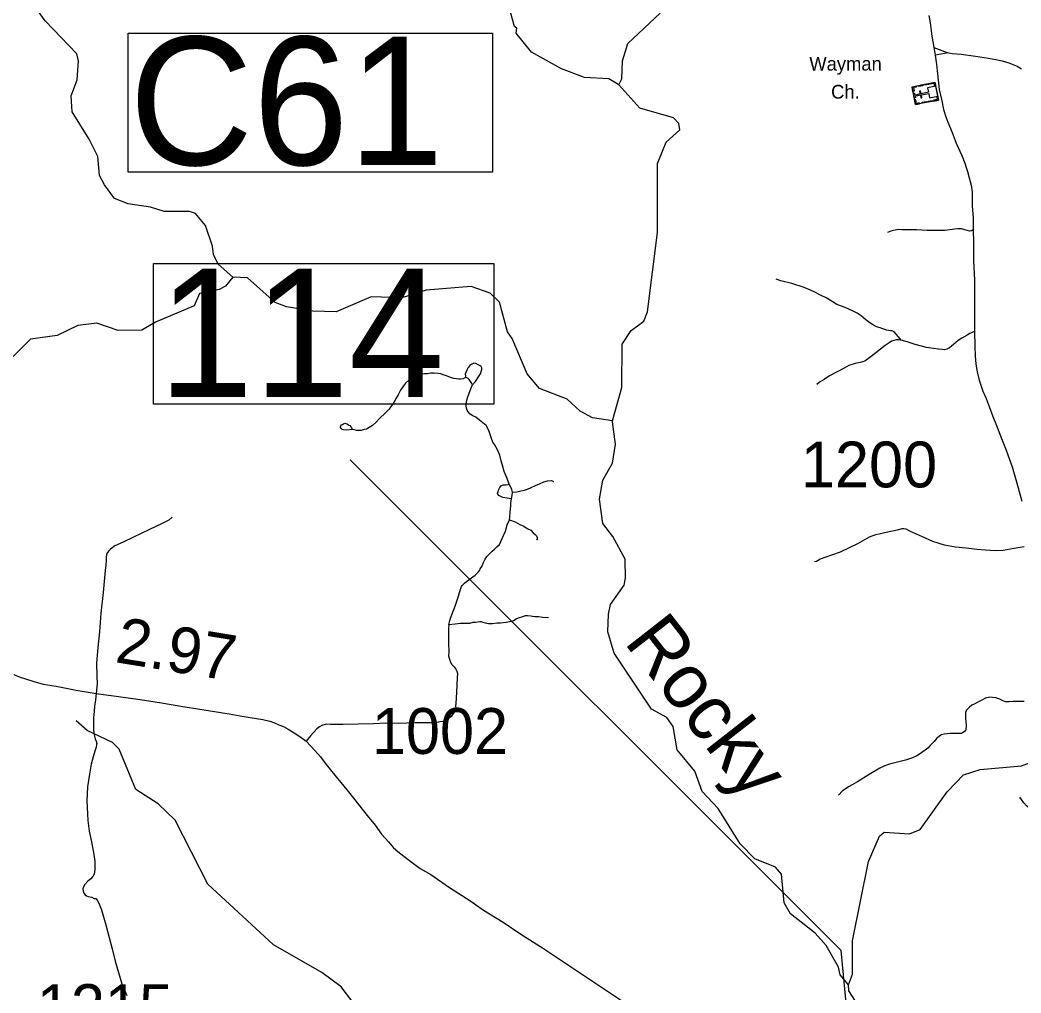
# Model space of a CAD drawing. Extents: x 2290615 to 2522933, y 819489 to 1012715.
# Drawn here: x 2342087 to 2353015, y 905808 to 916430 of the extents above; entities that cross this region are included whole.
import ezdxf

# ---------------------------------------------------------------- set-up
doc = ezdxf.new("R2010")
doc.units = 0
for name, color, linetype in [('Exist Cultural Church Label', 7, 'Continuous'), ('Exist Cultural Church with Cemetery CELL', 7, 'Continuous'), ('Exist Hydrographic Creek Single Shore', 7, 'Continuous'), ('Exist Hydrographic Creek Single Shore Label', 7, 'Continuous'), ('Exist Hydrographic Misc Water Feature', 7, 'Continuous'), ('Exist Road Non-System Type 51', 7, 'Continuous'), ('Exist Road Primary NC Structure Culvert Number Label', 7, 'Continuous'), ('Exist Road Secondary Mileage Hundredths English Label', 7, 'Continuous'), ('Exist Road Secondary Structure Standard Bridge Number Label', 7, 'Continuous'), ('Exist Road Secondary Type 51 Attributed', 7, 'Continuous'), ('Exist Road Secondary Type 51 Number Label', 7, 'Continuous')]:
    doc.layers.add(name, color=color, linetype=linetype)

msp = doc.modelspace()

# ---------------------------------------------------------------- linework, layer by layer
at = {"layer": 'Exist Cultural Church with Cemetery CELL'}
for points in [[(2351864, 915507), (2351827, 915702), (2352076, 915751), (2352114, 915555)], [(2351869, 915711), (2351871, 915699), (2351840, 915693), (2351847, 915654), (2351836, 915651), (2351827, 915702)], [(2352106, 915598), (2352085, 915708), (2351996, 915691), (2352006, 915641), (2351926, 915625), (2351919, 915658), (2351908, 915655), (2351915, 915623), (2351873, 915615), (2351876, 915604), (2351917, 915612), (2351923, 915579), (2351934, 915581), (2351928, 915614), (2352008, 915629), (2352017, 915580)], [(2351943, 915713), (2351900, 915705), (2351898, 915716), (2351941, 915725)], [(2352008, 915726), (2351965, 915718), (2351963, 915729), (2352006, 915737)], [(2352083, 915718), (2352072, 915716), (2352067, 915738), (2352028, 915730), (2352026, 915741), (2352076, 915751)], [(2351850, 915580), (2351840, 915630), (2351852, 915633), (2351862, 915582)], [(2351907, 915515), (2351905, 915526), (2351873, 915520), (2351866, 915560), (2351855, 915558), (2351864, 915507)], [(2351980, 915529), (2351937, 915521), (2351935, 915532), (2351978, 915540)], [(2352046, 915542), (2352003, 915534), (2352001, 915545), (2352044, 915553)], [(2352108, 915588), (2352097, 915586), (2352101, 915564), (2352061, 915556), (2352063, 915545), (2352114, 915555)]]:
    msp.add_lwpolyline(points, close=True, dxfattribs=at)
at = {"layer": 'Exist Hydrographic Creek Single Shore'}
for points in [[(2348626, 915722), (2348517, 915789), (2348250, 915801), (2347999, 915899), (2347672, 916080), (2347503, 916286), (2347511, 916342), (2347485, 916361), (2347398, 916676)], [(2348554, 912056), (2348657, 912418), (2348660, 912890), (2348758, 913042), (2348899, 913143), (2348939, 913243), (2349045, 914111), (2349045, 914863), (2349142, 915096), (2349290, 915230), (2349281, 915299), (2349222, 915362), (2348854, 915469), (2348626, 915722)], [(2351133, 905898), (2351040, 906006), (2351023, 906091), (2350887, 906328), (2350768, 906461), (2350499, 906673), (2350431, 906792), (2350402, 907106), (2350335, 907182), (2350109, 907271), (2349948, 907435), (2349710, 907823), (2349533, 908006), (2349456, 908229), (2349261, 908461), (2349216, 908718), (2349149, 908817), (2348981, 908906), (2348574, 909519), (2348504, 909749), (2348510, 909943), (2348534, 910049), (2348681, 910262), (2348697, 910335), (2348695, 910545), (2348558, 910792), (2348448, 910932), (2348412, 911200), (2348451, 911408), (2348557, 911593), (2348588, 911801), (2348556, 912045)], [(2351796, 904806), (2351134, 905833), (2351133, 905898)]]:
    msp.add_lwpolyline(points, dxfattribs=at)
at = {"layer": 'Exist Hydrographic Misc Water Feature'}
msp.add_line((2348556, 912045), (2348554, 912056), dxfattribs=at)
for points in [[(2344411, 913622), (2344251, 913763), (2344200, 913869), (2344190, 913961), (2344113, 914187), (2344003, 914317), (2343936, 914341), (2343661, 914340), (2343511, 914386), (2343268, 914425), (2343118, 914481), (2343008, 914631), (2342956, 914731), (2342937, 914940), (2342843, 915130), (2342656, 915427), (2342646, 915601), (2342711, 915778), (2342725, 915985), (2342707, 916060), (2342361, 916423), (2342192, 916662)], [(2348626, 915722), (2348659, 915789), (2348665, 915983), (2348721, 916175), (2349075, 916505)], [(2344411, 913622), (2344329, 913523), (2344263, 913488), (2344046, 913443), (2343990, 913309), (2343567, 913131), (2343418, 913046), (2343160, 913042), (2342926, 913121), (2342718, 913096), (2342494, 912985), (2342203, 912947), (2341775, 912526)], [(2348554, 912056), (2348336, 912086), (2348202, 912159), (2348059, 912291), (2347758, 912407), (2347623, 912569), (2347460, 912953), (2347409, 913026), (2347322, 913351), (2347221, 913448), (2347011, 913522), (2346520, 913482), (2346255, 913396), (2345921, 913408), (2345540, 913245), (2345282, 913251), (2344998, 913298), (2344873, 913346), (2344569, 913615), (2344411, 913622)], [(2345720, 905709), (2345594, 905875), (2345383, 906030), (2344855, 906333), (2344139, 906997), (2343781, 907694), (2343595, 907874), (2343352, 908031), (2343171, 908470), (2343095, 908543), (2342819, 908672), (2342701, 908779)], [(2351133, 905898), (2351174, 906015), (2351177, 906376), (2351350, 907243), (2351472, 907521), (2351522, 907562), (2351797, 907547), (2351913, 907591), (2352208, 908004), (2352389, 908189), (2352571, 908249), (2353021, 908287), (2353477, 908460), (2353643, 908454), (2353869, 908374), (2354172, 908154), (2354505, 908174), (2355066, 907914), (2355225, 907891)]]:
    msp.add_lwpolyline(points, dxfattribs=at)
at = {"layer": 'Exist Road Non-System Type 51'}
msp.add_line((2352223, 916071), (2352077, 916045), dxfattribs=at)
for points in [[(2352492, 914140), (2352475, 914127), (2352454, 914125), (2352403, 914138), (2352366, 914149), (2352325, 914150), (2352288, 914148), (2352184, 914134), (2352062, 914132), (2351989, 914134), (2351874, 914138), (2351762, 914139), (2351715, 914141), (2351678, 914142), (2351659, 914141), (2351623, 914134), (2351594, 914124), (2351559, 914112)], [(2351706, 912935), (2351679, 912970), (2351653, 913001), (2351631, 913027), (2351609, 913036), (2351589, 913036), (2351567, 913039), (2351545, 913045), (2351479, 913070), (2351439, 913081), (2351403, 913099), (2351366, 913124), (2351320, 913158), (2351269, 913199), (2351227, 913231), (2351181, 913252), (2351094, 913291), (2351006, 913324), (2350952, 913357), (2350887, 913396), (2350833, 913424), (2350750, 913465), (2350648, 913511), (2350515, 913552), (2350393, 913582), (2350341, 913600)], [(2352508, 913028), (2352457, 913008), (2352427, 912989), (2352370, 912957), (2352329, 912931), (2352279, 912886), (2352236, 912853), (2352205, 912836), (2352180, 912831), (2352155, 912834), (2352114, 912835), (2352060, 912843), (2351983, 912854), (2351861, 912886), (2351785, 912913), (2351747, 912925), (2351706, 912935)], [(2351706, 912935), (2351679, 912938), (2351653, 912938), (2351603, 912923), (2351576, 912906), (2351532, 912875), (2351480, 912837), (2351380, 912756), (2351311, 912706), (2351261, 912693), (2351204, 912681), (2351136, 912660), (2351085, 912630), (2351002, 912587), (2350924, 912545), (2350865, 912507), (2350816, 912475), (2350786, 912452)], [(2347028, 912446), (2347058, 912483), (2347093, 912536), (2347114, 912568), (2347123, 912593), (2347130, 912619), (2347130, 912633), (2347122, 912646), (2347110, 912656), (2347088, 912667), (2347062, 912682), (2347041, 912684), (2347018, 912672), (2346997, 912658), (2346980, 912636), (2346964, 912609), (2346953, 912583), (2346948, 912565), (2346951, 912545), (2346949, 912526)], [(2346949, 912526), (2346925, 912514), (2346896, 912511), (2346878, 912510), (2346853, 912513), (2346823, 912516), (2346788, 912527), (2346743, 912545), (2346705, 912557), (2346683, 912567), (2346652, 912571), (2346609, 912573), (2346572, 912576), (2346536, 912568), (2346504, 912568), (2346484, 912565), (2346461, 912563), (2346439, 912557), (2346414, 912549), (2346387, 912537), (2346364, 912523), (2346331, 912498), (2346297, 912466), (2346274, 912436), (2346242, 912389), (2346214, 912339), (2346193, 912301), (2346172, 912262), (2346156, 912238), (2346134, 912210), (2346117, 912182), (2346076, 912140), (2346012, 912080), (2345975, 912039), (2345936, 912002), (2345900, 911982), (2345871, 911964), (2345843, 911958), (2345812, 911950), (2345781, 911948), (2345760, 911950), (2345731, 911955), (2345712, 911959)], [(2347028, 912446), (2347013, 912472), (2346990, 912505), (2346979, 912518), (2346966, 912524), (2346949, 912526)], [(2347428, 911362), (2347405, 911426), (2347374, 911500), (2347359, 911556), (2347341, 911618), (2347324, 911678), (2347299, 911736), (2347281, 911772), (2347267, 911795), (2347250, 911823), (2347231, 911873), (2347208, 911937), (2347192, 911979), (2347176, 912002), (2347140, 912033), (2347102, 912060), (2347062, 912093), (2347024, 912111), (2346997, 912130), (2346979, 912151), (2346969, 912169), (2346962, 912191), (2346959, 912217), (2346958, 912238), (2346962, 912267), (2346971, 912304), (2346990, 912355), (2347010, 912402), (2347021, 912431), (2347028, 912446)], [(2345712, 911959), (2345679, 911955), (2345646, 911951), (2345620, 911956), (2345603, 911959), (2345593, 911971), (2345586, 911981), (2345585, 911990), (2345588, 912000), (2345596, 912010), (2345606, 912016), (2345620, 912023), (2345633, 912028), (2345645, 912025), (2345659, 912021), (2345677, 912008), (2345687, 912002), (2345700, 911990), (2345707, 911981), (2345710, 911971), (2345712, 911959)], [(2347465, 911274), (2347511, 911279), (2347555, 911291), (2347595, 911297), (2347626, 911308), (2347667, 911326), (2347714, 911347), (2347760, 911367), (2347805, 911390), (2347847, 911398), (2347890, 911403), (2347911, 911391)], [(2347454, 911203), (2347407, 911209), (2347359, 911219), (2347337, 911227), (2347315, 911238), (2347302, 911253), (2347301, 911266), (2347306, 911282), (2347312, 911299), (2347324, 911325), (2347341, 911346), (2347361, 911354), (2347387, 911357), (2347411, 911360), (2347428, 911362)], [(2347465, 911274), (2347455, 911305), (2347441, 911336), (2347428, 911362)], [(2347454, 911203), (2347459, 911240), (2347465, 911274)], [(2347431, 910975), (2347436, 911006), (2347439, 911058), (2347446, 911128), (2347447, 911164), (2347454, 911203)], [(2343749, 911004), (2343710, 910971), (2343638, 910934), (2343500, 910869), (2343411, 910823), (2343318, 910781), (2343212, 910731), (2343121, 910688), (2343076, 910654), (2343053, 910633), (2343033, 910607), (2343028, 910571), (2343027, 910526), (2343023, 910482), (2343017, 910420), (2342996, 910181), (2342971, 909954), (2342954, 909752), (2342937, 909580), (2342923, 909409), (2342924, 909266), (2342931, 909184), (2342918, 909077), (2342910, 909007), (2342901, 908940), (2342897, 908883), (2342888, 908812), (2342891, 908762), (2342888, 908714), (2342891, 908678), (2342898, 908626), (2342909, 908583), (2342919, 908556), (2342925, 908532), (2342923, 908519), (2342918, 908492), (2342904, 908449), (2342886, 908385), (2342862, 908305), (2342844, 908198), (2342825, 908057), (2342818, 907906), (2342822, 907762), (2342828, 907690), (2342841, 907576), (2342867, 907457), (2342885, 907359), (2342894, 907319), (2342902, 907242), (2342904, 907157), (2342896, 907104), (2342881, 907079), (2342860, 907053), (2342828, 907028), (2342796, 906994), (2342781, 906968), (2342773, 906944), (2342777, 906918), (2342784, 906898), (2342798, 906880), (2342812, 906868), (2342832, 906861), (2342872, 906853), (2342898, 906841), (2342916, 906838), (2342928, 906822), (2342949, 906788), (2342978, 906716), (2343024, 906553), (2343059, 906415), (2343093, 906290), (2343124, 906156), (2343164, 906031), (2343199, 905909), (2343253, 905780)], [(2346770, 909831), (2346780, 909875), (2346795, 909918), (2346816, 909977), (2346836, 910032), (2346858, 910098), (2346873, 910140), (2346886, 910181), (2346901, 910224), (2346907, 910244), (2346915, 910257), (2346928, 910270), (2346940, 910281), (2346962, 910301), (2346997, 910324), (2347032, 910350), (2347055, 910368), (2347075, 910386), (2347089, 910403), (2347106, 910423), (2347110, 910439), (2347127, 910465), (2347148, 910508), (2347167, 910543), (2347185, 910573), (2347210, 910599), (2347242, 910631), (2347268, 910654), (2347293, 910677), (2347320, 910705), (2347335, 910736), (2347364, 910801), (2347389, 910851), (2347407, 910918), (2347431, 910975)], [(2347431, 910975), (2347494, 910950), (2347543, 910924), (2347589, 910903), (2347624, 910880), (2347665, 910859), (2347690, 910832), (2347712, 910815), (2347727, 910797), (2347733, 910779), (2347733, 910762), (2347727, 910750)], [(2353048, 910678), (2352939, 910660), (2352821, 910640), (2352732, 910635), (2352623, 910642), (2352533, 910650), (2352416, 910665), (2352301, 910676), (2352181, 910696), (2352053, 910738), (2351940, 910787), (2351807, 910847), (2351761, 910871), (2351731, 910877), (2351713, 910874), (2351677, 910864), (2351631, 910854), (2351524, 910833), (2351466, 910818), (2351427, 910811), (2351359, 910783), (2351229, 910713), (2351042, 910619), (2350874, 910564), (2350821, 910543), (2350800, 910530), (2350782, 910520), (2350760, 910515)], [(2346770, 909831), (2346839, 909837), (2346897, 909844), (2346956, 909845), (2346997, 909847), (2347036, 909855), (2347060, 909858), (2347081, 909860), (2347106, 909863), (2347122, 909862), (2347140, 909858), (2347164, 909850), (2347185, 909847), (2347202, 909842), (2347221, 909840), (2347247, 909842), (2347293, 909848), (2347333, 909850), (2347394, 909858), (2347431, 909865), (2347455, 909866), (2347473, 909875), (2347502, 909891), (2347530, 909904), (2347577, 909917), (2347607, 909928), (2347629, 909928), (2347662, 909925), (2347681, 909920), (2347711, 909917), (2347748, 909918), (2347795, 909912), (2347855, 909907)], [(2346770, 909831), (2346764, 909787), (2346764, 909726), (2346766, 909627), (2346767, 909534), (2346766, 909487), (2346772, 909463), (2346779, 909440), (2346787, 909419), (2346803, 909394), (2346827, 909368), (2346845, 909342), (2346857, 909320), (2346863, 909297), (2346861, 909250), (2346853, 909091), (2346846, 908969), (2346834, 908883), (2346795, 908828), (2346767, 908805), (2346736, 908781), (2346704, 908773), (2346672, 908768), (2346624, 908758), (2346526, 908758), (2346401, 908756), (2346220, 908751), (2346079, 908752), (2345947, 908747), (2345780, 908743), (2345612, 908738), (2345476, 908740), (2345430, 908743), (2345383, 908729), (2345355, 908714), (2345329, 908690), (2345260, 908615), (2345210, 908556)], [(2353048, 908990), (2353007, 908990), (2352959, 908989), (2352929, 908990), (2352886, 908987), (2352849, 908988), (2352815, 908999), (2352783, 909015), (2352742, 909030), (2352705, 909033), (2352674, 909036), (2352629, 909026), (2352573, 908997), (2352502, 908960), (2352480, 908949), (2352454, 908929), (2352419, 908896), (2352408, 908870), (2352408, 908807), (2352415, 908728), (2352413, 908680), (2352398, 908662), (2352384, 908650), (2352366, 908640), (2352324, 908639), (2352242, 908640), (2352175, 908632), (2352145, 908627), (2352120, 908609), (2352096, 908589), (2352066, 908555), (2352025, 908509), (2351997, 908479), (2351969, 908458), (2351933, 908434), (2351906, 908416), (2351877, 908398), (2351830, 908374), (2351754, 908351), (2351667, 908327), (2351581, 908305), (2351517, 908285), (2351474, 908264), (2351358, 908193), (2351229, 908114), (2351140, 908062), (2351065, 908015), (2351022, 907968)], [(2354052, 907806), (2353990, 907807), (2353904, 907825), (2353814, 907846), (2353801, 907847), (2353789, 907843), (2353776, 907834), (2353765, 907823), (2353744, 907814), (2353722, 907806), (2353688, 907804), (2353562, 907815), (2353469, 907818), (2353382, 907813), (2353332, 907823), (2353285, 907827), (2353221, 907823), (2353144, 907824), (2353111, 907827), (2353092, 907835), (2353076, 907851), (2353047, 907885), (2353001, 907945)]]:
    msp.add_lwpolyline(points, dxfattribs=at)
at = {"layer": 'Exist Road Primary NC Structure Culvert Number Label'}
msp.add_lwpolyline([(2343266, 916288), (2347247, 916288), (2347247, 914768), (2343266, 914768)], close=True, dxfattribs=at)
at = {"layer": 'Exist Road Secondary Structure Standard Bridge Number Label'}
msp.add_lwpolyline([(2343545, 913772), (2347261, 913772), (2347261, 912236), (2343545, 912236)], close=True, dxfattribs=at)
msp.add_lwpolyline([(2351267, 904026), (2351050, 906271), (2345693, 911628)], dxfattribs=at)
at = {"layer": 'Exist Road Secondary Type 51 Attributed'}
for points in [[(2352009, 916480), (2352025, 916398), (2352042, 916254), (2352063, 916131)], [(2352063, 916131), (2352209, 916076), (2352263, 916064), (2352361, 916056), (2352519, 916037), (2352659, 916015), (2352757, 915994), (2352810, 915983), (2352882, 915963), (2352975, 915926), (2353021, 915898)], [(2352063, 916131), (2352077, 916045), (2352094, 915943), (2352105, 915843), (2352123, 915670), (2352149, 915549), (2352170, 915453), (2352195, 915372), (2352217, 915314), (2352263, 915201), (2352308, 915084), (2352368, 914950), (2352401, 914866), (2352418, 914819), (2352432, 914776), (2352450, 914709), (2352471, 914627), (2352481, 914556), (2352482, 914399), (2352493, 914273), (2352492, 914140), (2352497, 913999), (2352497, 913801), (2352506, 913591), (2352506, 913387), (2352506, 913181), (2352508, 913028), (2352510, 912866), (2352513, 912765), (2352521, 912672), (2352536, 912590), (2352558, 912497), (2352599, 912377), (2352636, 912297), (2352666, 912211), (2352707, 912101), (2352748, 912003), (2352803, 911863), (2352853, 911734), (2352920, 911553), (2352966, 911388), (2353024, 911179)], [(2342021, 909284), (2342087, 909255), (2342148, 909236), (2342228, 909211), (2342338, 909180), (2342483, 909156), (2342700, 909114), (2342918, 909077), (2343164, 909046), (2343398, 909013), (2343630, 908976), (2343865, 908936), (2344051, 908907), (2344370, 908854), (2344490, 908832), (2344600, 908815), (2344738, 908793), (2344816, 908774), (2344867, 908758), (2344911, 908737), (2344963, 908716), (2345015, 908688), (2345080, 908647), (2345141, 908608), (2345210, 908556), (2345262, 908502), (2345306, 908455), (2345366, 908385), (2345428, 908302), (2345538, 908169), (2345672, 908004), (2345781, 907864), (2345878, 907746), (2345963, 907640), (2346034, 907542), (2346109, 907458), (2346165, 907393), (2346210, 907353), (2346277, 907301), (2346339, 907253), (2346455, 907168), (2346571, 907100), (2346765, 906966), (2347007, 906811), (2347148, 906712), (2347360, 906580), (2347554, 906450), (2347791, 906300), (2348666, 905717)]]:
    msp.add_lwpolyline(points, dxfattribs=at)

# ---------------------------------------------------------------- texts
at = {"layer": 'Exist Cultural Church Label'}
for s, p in [('Wayman', (2350704, 915878)), ('Ch.', (2350942, 915572))]:
    msp.add_text(s, height=150, rotation=360, dxfattribs=at).set_placement(p)
at = {"layer": 'Exist Hydrographic Creek Single Shore Label'}
msp.add_text('Rocky', height=600, rotation=307.9907, dxfattribs=at).set_placement((2348672, 909638))
at = {"layer": 'Exist Road Primary NC Structure Culvert Number Label'}
msp.add_text('C61', height=1400, dxfattribs=at).set_placement((2343279, 914847))
at = {"layer": 'Exist Road Secondary Mileage Hundredths English Label'}
msp.add_text('2.97', height=500, rotation=350.6927, dxfattribs=at).set_placement((2343114, 909421))
at = {"layer": 'Exist Road Secondary Structure Standard Bridge Number Label'}
msp.add_text('114', height=1400, dxfattribs=at).set_placement((2343595, 912315))
at = {"layer": 'Exist Road Secondary Type 51 Number Label'}
for s, p in [('1200', (2350612, 911328)), ('1002', (2345928, 908418)), ('1215', (2342270, 905404))]:
    msp.add_text(s, height=500, rotation=360, dxfattribs=at).set_placement(p)

doc.saveas('drawing.dxf')
